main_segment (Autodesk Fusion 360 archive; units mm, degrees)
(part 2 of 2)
sketch "hes slots" plane through (0, -21.9998, 0) normal (0, -1, 0) x axis (1, 0, 0)
  line L1 (261.226, 171.719) -> (259.326, 168.4281)
  line L2 (259.326, 175.0099) -> (261.226, 171.719)
  line L3 (255.526, 175.0099) -> (259.326, 175.0099)
  line L4 (253.626, 171.719) -> (255.526, 175.0099)
  line L5 (255.526, 168.4281) -> (253.626, 171.719)
  line L6 (259.326, 168.4281) -> (255.526, 168.4281)
  line L7 (249.7983, 177.1307) -> (250.2985, 176.2642)
  line L8 (253.67, 180.982) -> (250.311, 179.0427)
  line L9 (259.5563, 179.8293) -> (254.7324, 181.1219)
  line L10 (259.6429, 179.8793) -> (259.5563, 179.8293)
  line L11 (285.6015, 134.9177) -> (259.6429, 179.8793)
  line L12 (285.5149, 134.8677) -> (285.6015, 134.9177)
  line L13 (284.2223, 130.0438) -> (285.5149, 134.8677)
  line L14 (280.211, 127.2543) -> (283.57, 129.1937)
  line L15 (277.7985, 128.6328) -> (278.2985, 127.7668)
  line L16 (274.7469, 128.7184) -> (275.6129, 129.2184)
  line L17 (274.6612, 125.6668) -> (274.1612, 126.5328)
  line L18 (269.9808, 121.3479) -> (274.1488, 123.7543)
  line L19 (270.7612, 118.7963) -> (269.7612, 120.5283)
  line L20 (269.3827, 116.3838) -> (270.2487, 116.8838)
  line L21 (234.9703, 173.1879) -> (267.4703, 116.8963)
  line L22 (236.3487, 175.6003) -> (235.4827, 175.1003)
  line L23 (239.2612, 173.3559) -> (238.2612, 175.0879)
  line L24 (244.2488, 175.5427) -> (240.0808, 173.1362)
  line L25 (246.6612, 174.1642) -> (246.1612, 175.0302)
  line L26 (249.7129, 174.0786) -> (248.8469, 173.5786)
  line L27 (249.8745, 174.1858) -> (249.7129, 174.0786)
  line L28 (250.2988, 176.2638) -> (250.344, 176.1855)
  line L29 (250.8337, 165.719) -> (248.9337, 162.4281)
  line L30 (248.9337, 169.0099) -> (250.8337, 165.719)
  line L31 (245.1337, 169.0099) -> (248.9337, 169.0099)
  line L32 (243.2337, 165.719) -> (245.1337, 169.0099)
  line L33 (245.1337, 162.4281) -> (243.2337, 165.719)
  line L34 (248.9337, 162.4281) -> (245.1337, 162.4281)
  line L35 (263.2337, 131.078) -> (265.1337, 134.3689)
  line L36 (265.1337, 127.7871) -> (263.2337, 131.078)
  line L37 (268.9337, 127.7871) -> (265.1337, 127.7871)
  line L38 (270.8337, 131.078) -> (268.9337, 127.7871)
  line L39 (268.9337, 134.3689) -> (270.8337, 131.078)
  line L40 (265.1337, 134.3689) -> (268.9337, 134.3689)
  line L41 (273.626, 137.078) -> (275.526, 140.3689)
  line L42 (275.526, 133.7871) -> (273.626, 137.078)
  line L43 (279.326, 133.7871) -> (275.526, 133.7871)
  line L44 (281.226, 137.078) -> (279.326, 133.7871)
  line L45 (279.326, 140.3689) -> (281.226, 137.078)
  line L46 (275.526, 140.3689) -> (279.326, 140.3689)
  line L47 (288.3901, 126.0876) -> (253.3901, 186.7094)
  line L48 (189.1191, 226.8415) -> (188.3554, 223.119)
  line L49 (186.2772, 229.3641) -> (189.1191, 226.8415)
  line L50 (182.6716, 228.1642) -> (186.2772, 229.3641)
  line L51 (181.9079, 224.4418) -> (182.6716, 228.1642)
  line L52 (184.7498, 221.9192) -> (181.9079, 224.4418)
  line L53 (188.3554, 223.119) -> (184.7498, 221.9192)
  line L54 (212.1304, 200.7849) -> (215.8279, 201.6616)
  line L55 (211.041, 197.1444) -> (212.1304, 200.7849)
  line L56 (213.6491, 194.3807) -> (211.041, 197.1444)
  line L57 (217.3465, 195.2575) -> (213.6491, 194.3807)
  line L58 (218.4359, 198.8979) -> (217.3465, 195.2575)
  line L59 (215.8279, 201.6616) -> (218.4359, 198.8979)
  line L60 (275.1563, 87.8062) -> (277.7427, 90.5902)
  line L61 (276.2743, 84.1743) -> (275.1563, 87.8062)
  line L62 (279.9785, 83.3266) -> (276.2743, 84.1743)
  line L63 (282.5648, 86.1106) -> (279.9785, 83.3266)
  line L64 (281.4469, 89.7425) -> (282.5648, 86.1106)
  line L65 (277.7427, 90.5902) -> (281.4469, 89.7425)
  line L66 (284.5943, 49.13) -> (287.4996, 51.5793)
  line L67 (285.2629, 45.3893) -> (284.5943, 49.13)
  line L68 (288.8367, 44.0979) -> (285.2629, 45.3893)
  line L69 (291.742, 46.5472) -> (288.8367, 44.0979)
  line L70 (291.0735, 50.288) -> (291.742, 46.5472)
  line L71 (287.4996, 51.5793) -> (291.0735, 50.288)
  circle C1 centre (257.426, 171.719) radius 2.05
  circle C2 centre (247.0337, 165.719) radius 2.05
  circle C3 centre (277.426, 137.078) radius 2.05
  circle C4 centre (267.0337, 131.078) radius 2.05
  arc A1 centre (251.011, 177.8302) radius 1.4 clockwise from (249.7983, 177.1307) to (250.311, 179.0427)
  arc A2 centre (254.37, 179.7696) radius 1.4 clockwise from (253.67, 180.982) to (254.7324, 181.1219)
  arc A3 centre (282.87, 130.4061) radius 1.4 clockwise from (284.2223, 130.0438) to (283.57, 129.1937)
  arc A4 centre (279.511, 128.4668) radius 1.4 clockwise from (280.211, 127.2543) to (278.2985, 127.7668)
  arc A5 centre (276.4129, 127.8328) radius 1.6 clockwise from (275.6129, 129.2184) to (277.7985, 128.6328)
  arc A6 centre (275.5469, 127.3328) radius 1.6 clockwise from (274.1612, 126.5328) to (274.7469, 128.7184)
  arc A7 centre (273.4488, 124.9668) radius 1.4 clockwise from (274.6612, 125.6668) to (274.1488, 123.7543)
  arc A8 centre (270.2808, 120.8283) radius 0.6 clockwise from (269.7612, 120.5283) to (269.9808, 121.3479)
  arc A9 centre (269.5487, 118.0963) radius 1.4 clockwise from (270.7612, 118.7963) to (270.2487, 116.8838)
  arc A10 centre (268.6827, 117.5963) radius 1.4 clockwise from (269.3827, 116.3838) to (267.4703, 116.8963)
  arc A11 centre (236.1827, 173.8879) radius 1.4 clockwise from (234.9703, 173.1879) to (235.4827, 175.1003)
  arc A12 centre (237.0487, 174.3879) radius 1.4 clockwise from (236.3487, 175.6003) to (238.2612, 175.0879)
  arc A13 centre (239.7808, 173.6559) radius 0.6 clockwise from (240.0808, 173.1362) to (239.2612, 173.3559)
  arc A14 centre (244.9488, 174.3302) radius 1.4 clockwise from (244.2488, 175.5427) to (246.1612, 175.0302)
  arc A15 centre (248.0469, 174.9642) radius 1.6 clockwise from (248.8469, 173.5786) to (246.6612, 174.1642)
  arc A16 centre (249.0449, 175.4355) radius 1.5 clockwise from (250.344, 176.1855) to (249.8745, 174.1858)
  arc A17 centre (248.9129, 175.4642) radius 1.6 clockwise from (250.2985, 176.2642) to (250.2988, 176.2638)
  circle C5 centre (185.5135, 225.6416) radius 2
  circle C6 centre (214.7385, 198.0212) radius 2
  circle C7 centre (278.8606, 86.9584) radius 2
  circle C8 centre (288.1682, 47.8386) radius 2
  point P8 (257.426, 171.719)
  point P9 (257.426, 171.719)
  point P10 (247.0337, 165.719)
  point P75 (247.0337, 165.719)
  point P12 (267.0337, 131.078)
  point P82 (267.0337, 131.078)
  point P11 (277.426, 137.078)
  point P89 (277.426, 137.078)
  point P98 (185.5135, 225.6416)
  point P120 (185.5135, 225.6416)
  point P105 (214.7385, 198.0212)
  point P121 (214.7385, 198.0212)
  point P112 (278.8606, 86.9584)
  point P122 (278.8606, 86.9584)
  point P119 (288.1682, 47.8386)
  point P123 (288.1682, 47.8386)
  point P2 (259.326, 168.4281)
  point P69 (248.9337, 162.4281)
  point P76 (265.1337, 134.3689)
  point P83 (275.526, 140.3689)
  point P92 (188.3554, 223.119)
  point P99 (215.8279, 201.6616)
  point P106 (277.7427, 90.5902)
  point P113 (287.4996, 51.5793)
  coincident P8 P9
  coincident P10 P75
  coincident P12 P82
  coincident P11 P89
  parallel L2 L47
  parallel L45 L47
  parallel L39 L47
  parallel L30 L47
  coincident P98 P120
  coincident P105 P121
  coincident P112 P122
  coincident P119 P123
  dimension "d244" distance P2 P8 = 3.8
  dimension "d245" distance P69 P75 = 3.8
  dimension "d246" distance P76 P82 = 3.8
  dimension "d247" distance P83 P89 = 3.8
  dimension "d250" distance P92 P98 = 3.8
  dimension "d251" distance P99 P105 = 3.8
  dimension "d252" distance P106 P112 = 3.8
  dimension "d253" distance P113 P119 = 3.8
extrude "Extrude17" cut sketch "hes slots" profile of L60 L61 L62 L63 L64 L65 L66 L67 L68 L69 L70 L71 blind -6 from offset -10
extrude "Extrude16" cut sketch "hes slots" profile of L1 L2 L3 L4 L5 L6 C1 C2 C3 C4 L29 L30 L31 L32 L33 L34 L35 L36 L37 L38 L39 L40 L41 L42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 against normal blind 2
extrude "Extrude18" cut sketch "hes slots" profile of L48 L49 L50 L51 L52 L53 L54 L55 L56 L57 L58 L59 C5 C6 against normal blind 7
sketch "small pocket" plane through (0, 0.0002, 0) normal (0, 1, 0) x axis (-1, 0, 0)
  line L1 (-144.1577, 247.6885) -> (-142.7926, 247.324)
  line L2 (-170.2702, 243.9555) -> (-163.9732, 235.0401)
  line L3 (-158.9396, 253.2593) -> (-158.1458, 251.9845)
  line L4 (-159.7885, 252.7308) -> (-158.9396, 253.2593)
  line L5 (-171.1402, 245.1776) -> (-159.7885, 252.7308)
  curve K1 (-254.2562, 187.2094) -> (-172.5326, 245.4252)
  line L6 (-256.7562, 182.8793) -> (-254.2562, 187.2094)
  line L7 (-241.3298, 173.9728) -> (-256.7562, 182.8793)
  line L8 (-174.3946, 227.5779) -> (-180.9692, 236.1462)
  line L9 (-294.8797, 38.6359) -> (-284.2856, 37.2412)
  line L10 (-296.7753, 20.7526) -> (-296.6755, 20.7456)
  line L11 (-294.9932, 38.6508) -> (-294.9788, 38.649)
  line L12 (-286.7562, 130.9177) -> (-271.3298, 122.0113)
  line L13 (-289.2562, 126.5876) -> (-286.7562, 130.9177)
  line L14 (-280.6738, 105.4667) -> (-284.1318, 107.4633)
  line L15 (-296.4, 0.9531) -> (-298.9985, 0.9531)
  line L16 (-296.4, 0) -> (-296.4, 0.9531)
  line L17 (-295.3663, -8.8866) -> (-296.2658, -8.9169)
  line L18 (-288.5852, 0) -> (-295.5, 0)
  line L19 (-286.9844, -20.0679) -> (-287.8822, -20.1307)
  line L20 (-286.0549, -19.0005) -> (-286.9844, -20.0679)
  line L21 (-287.0527, -19.0667) -> (-286.0549, -19.0005)
  line L22 (-287.6852, 0.8045) -> (-287.6852, 0)
  line L23 (-285.5841, 0.8045) -> (-287.6852, 0.8045)
  line L24 (-269.3835, 97.7936) -> (-269.4715, 97.8444)
  line L25 (-285.9868, 19.9981) -> (-285.8871, 19.9912)
  line L26 (-252.5241, 186.2094) -> (-240.9703, 179.5388)
  curve K2 (-174.1727, 244.2806) -> (-252.5241, 186.2094)
  line L27 (-182.7946, 238.5269) -> (-174.1727, 244.2806)
  line L28 (-284.1318, 107.4633) -> (-280.6738, 105.4667)
  line L29 (-286.7562, 130.9177) -> (-289.2562, 126.5876)
  line L30 (-286.7562, 130.9177) -> (-271.3298, 122.0113)
  line L31 (-283.1318, 109.1953) -> (-280.67, 107.774)
  line L32 (-286.5241, 127.3197) -> (-287.5241, 125.5876)
  line L33 (-285.1581, 127.6857) -> (-276.2573, 122.5468)
  line L34 (-274.9758, 118.8248) -> (-279.2428, 108.2653)
  arc A1 centre (0, 0) radius 285.5852 clockwise from (-285.5841, 0.8045) to (-142.7926, 247.324)
  arc A2 centre (0, 0) radius 286.5852 clockwise from (-163.9732, 235.0401) to (-144.1577, 247.6885)
  arc A3 centre (0, 0) radius 297.5 clockwise from (-170.2702, 243.9555) to (-158.1458, 251.9845)
  arc A4 centre (-171.7126, 245.9976) radius 1 clockwise from (-171.1402, 245.1776) to (-172.5326, 245.4252)
  arc A5 centre (0.1681, -0.0971) radius 297.6938 clockwise from (-241.3298, 173.9728) to (-180.9692, 236.1462)
  arc A6 centre (0.1681, -0.0971) radius 286.8938 clockwise from (-284.2856, 37.2412) to (-174.3946, 227.5779)
  arc A7 centre (0, 0) radius 297.4 clockwise from (-296.6755, 20.7456) to (-294.8797, 38.6359)
  arc A8 centre (0, 0) radius 297.5 clockwise from (-296.7753, 20.7526) to (-294.9788, 38.649)
  arc A9 centre (0.1681, -0.0971) radius 297.6938 clockwise from (-294.9932, 38.6508) to (-271.3298, 122.0113)
  arc A10 centre (-277.1318, 119.5876) radius 14 clockwise from (-284.1318, 107.4633) to (-289.2562, 126.5876)
  arc A11 centre (-281.1738, 104.6007) radius 1 clockwise from (-280.6738, 105.4667) to (-280.2365, 104.2521)
  arc A12 centre (0, 0) radius 299 clockwise from (-298.9985, 0.9531) to (-280.2365, 104.2521)
  arc A13 centre (0, 0) radius 296.4 clockwise from (-296.2658, -8.9169) to (-296.4, 0)
  arc A14 centre (0, 0) radius 295.5 clockwise from (-295.3663, -8.8866) to (-295.5, 0)
  arc A15 centre (0, 0) radius 288.5852 clockwise from (-287.8822, -20.1307) to (-288.5852, 0)
  arc A16 centre (0, 0) radius 287.6852 clockwise from (-287.0527, -19.0667) to (-287.6852, 0)
  arc A17 centre (0, 0) radius 286.6852 clockwise from (-285.9868, 19.9981) to (-269.4715, 97.8444)
  arc A18 centre (0, 0) radius 286.5852 clockwise from (-285.8871, 19.9912) to (-269.3835, 97.7936)
  arc A19 centre (0.1681, -0.0971) radius 300.6938 clockwise from (-240.9703, 179.5388) to (-182.7946, 238.5269)
  arc A20 centre (-277.1318, 119.5876) radius 14 clockwise from (-284.1318, 107.4633) to (-289.2562, 126.5876)
  arc A21 centre (-277.1318, 119.5876) radius 12 clockwise from (-283.1318, 109.1953) to (-287.5241, 125.5876)
  arc A22 centre (-277.7573, 119.9487) radius 3 clockwise from (-276.2573, 122.5468) to (-274.9758, 118.8248)
  arc A23 centre (-280.17, 108.64) radius 1 clockwise from (-279.2428, 108.2653) to (-280.67, 107.774)
  arc A24 centre (-285.6581, 126.8197) radius 1 clockwise from (-286.5241, 127.3197) to (-285.1581, 127.6857)
  parallel L28 L31
  concentric A20 A21
  parallel L29 L32
  parallel L30 L33
  tangent L31 A21
  tangent A21 L32
  tangent L34 A22
  tangent L33 A22
  tangent L31 A23
  tangent L34 A23
  tangent L32 A24
  tangent L33 A24
  equal A23 A24
  dimension "d260" radius A22 = 3
  dimension "d261" radius A23 = 1
extrude "Extrude19" cut sketch "small pocket" profile of L31 A21 L32 L33 L34 A22 A23 A24 against normal blind 19
fillet "Fillet1" radius 1
extrude "Extrude20" cut sketch "small pocket" profile of L31 A21 L32 L33 L34 A22 A23 A24 along normal blind 18
fillet "Fillet2" radius 1
sketch "screw holes" plane through (0, 22.0002, 0) normal (0, 1, 0) x axis (-1, 0, 0)
  circle C1 centre (-257.426, 171.719) radius 2.05
  circle C2 centre (-277.426, 137.078) radius 2.05
  circle C3 centre (-185.5135, 225.6417) radius 2
  circle C4 centre (-214.7385, 198.0211) radius 2
  circle C5 centre (-247.0337, 165.719) radius 2.05
  circle C6 centre (-267.0337, 131.078) radius 2.05
  circle C7 centre (-278.8606, 86.9584) radius 2
  circle C8 centre (-288.1682, 47.8386) radius 2
  circle C9 centre (-185.5135, 225.6417) radius 3.5
  circle C10 centre (-214.7385, 198.0211) radius 3.5
  circle C11 centre (-247.0337, 165.719) radius 3.5
  circle C12 centre (-257.426, 171.719) radius 3.5
  circle C13 centre (-267.0337, 131.078) radius 3.5
  circle C14 centre (-277.426, 137.078) radius 3.5
  circle C15 centre (-278.8606, 86.9584) radius 3.5
  circle C16 centre (-288.1682, 47.8386) radius 3.5
  concentric C3 C9
  concentric C4 C10
  concentric C5 C11
  concentric C1 C12
  concentric C6 C13
  concentric C2 C14
  concentric C7 C15
  concentric C8 C16
  dimension "d268" diameter C9 = 7
  dimension "d269" diameter C10 = 7
  dimension "d270" diameter C11 = 7
  dimension "d271" diameter C12 = 7
  dimension "d272" diameter C13 = 7
  dimension "d273" diameter C14 = 7
  dimension "d274" diameter C15 = 7
  dimension "d275" diameter C16 = 7
extrude "Extrude21" cut sketch "screw holes" profile of C1 C2 C11 C12 C13 C14 against normal blind 5
extrude "Extrude22" cut sketch "screw holes" profile of C9 C10 against normal blind 9
extrude "Extrude23" cut sketch "screw holes" profile of C15 C16 against normal blind 16
chamfer "Chamfer4" distance 0.5
hole "Hole4" HoleDepth 6.2 HoleDiameter 7.5 TipAngle 180 RefDim1 10 RefDim2 35
hole "Hole2" HoleDepth 6.2 HoleDiameter 7.5 TipAngle 180
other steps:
create_component "CreateComponent1"
remove_body "RemoveBody1"
named bodies: "profile", "top", "bot", "mounting block"

design "mounting plate"
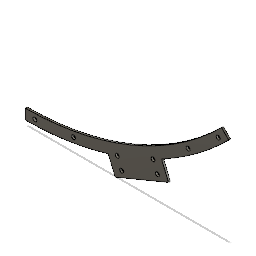
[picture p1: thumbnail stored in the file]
sketch "Sketch1" plane through (0, 0, 0) normal (0, 0, 1) x axis (1, 0, 0)
  line L1 (-0.1099, -297.6938) -> (-0.1099, -286.8938)
  line L2 (210.579, -210.4236) -> (202.9422, -202.7869)
  line L3 (202.9422, -202.7869) -> (-0.1099, -286.8938)
  line L4 (210.579, -210.4236) -> (-0.1099, -297.6938)
  line L5 (139.6676, -337.1874) -> (101.4162, -244.8403)
  line L6 (148.2583, -279.5334) -> (92.8255, -302.4944)
  line L7 (145.9622, -273.9901) -> (90.5294, -296.9511)
  line L8 (141.37, -262.9035) -> (85.9372, -285.8645)
  line L9 (141.0589, -262.1526) -> (148.2583, -279.5334)
  line L10 (92.8255, -302.4944) -> (85.6262, -285.1136)
  arc A1 centre (0, 0) radius 286.8938 clockwise from (202.9422, -202.7869) to (-0.1099, -286.8938)
  arc A2 centre (0, 0) radius 292.2938 clockwise from (206.7621, -206.6038) to (-0.1119, -292.2938)
  circle C1 centre (136.7234, -277.8169) radius 2
  circle C2 centre (99.7682, -293.1243) radius 2
  circle C3 centre (132.1312, -266.7304) radius 2
  circle C4 centre (95.176, -282.0377) radius 2
  circle C5 centre (199.5712, -213.558) radius 2
  circle C6 centre (168.3723, -238.9277) radius 2
  circle C7 centre (9.8901, -292.1264) radius 2
  circle C8 centre (49.8901, -288.0046) radius 2
  arc A3 centre (0, 0) radius 297.6938 clockwise from (85.6262, -285.1136) to (-0.1099, -297.6938)
  arc A4 centre (0, 0) radius 297.6938 clockwise from (210.579, -210.4236) to (141.0589, -262.1526)
  circle C9 centre (0, 0) radius 297.6938
  point P1 (0, 0)
  point P2 (0, 0)
  point P8 (101.4162, -244.8403)
  point P16 (145.9622, -273.9901)
  point P18 (141.37, -262.9035)
  point P19 (136.7234, -277.8169)
  point P20 (99.7682, -293.1243)
  point P21 (132.1312, -266.7304)
  point P22 (95.176, -282.0377)
  point P23 (199.5712, -213.558)
  point P24 (168.3723, -238.9277)
  point P25 (9.8901, -292.1264)
  point P26 (49.8901, -288.0046)
  point P27 (141.0589, -262.1526)
  point P13 (92.8255, -302.4944)
  point P14 (148.2583, -279.5334)
  coincident P1 P2
  concentric A1 A3
  vertical L1
  parallel L3 L4
  midpoint L3 P8
  perpendicular L4 L5
  perpendicular L4 L9
  midpoint L5 L6
  coincident P16 L9
  perpendicular L7 L9
  coincident P18 L9
  perpendicular L8 L9
  coincident L7 P19
  coincident L7 P20
  coincident L8 P21
  coincident L8 P22
  coincident A2 P23
  coincident A2 P24
  coincident A2 P25
  coincident A2 P26
  coincident P27 A3
  concentric A3 A4
  concentric A3 C9
  coincident P27 C9
  dimension "d3" angle L1 L2 = 45
  dimension "d4" = 5.4
  dimension "d5" distance P13 P14 = 60
  dimension "d6" distance L4 L6 = 40
  dimension "d7" distance L6 L7 = 6
  dimension "d8" distance L6 L8 = 18
  dimension "d9" diameter C1 = 4
  dimension "d10" diameter C2 = 4
  dimension "d11" diameter C3 = 4
  dimension "d12" diameter C4 = 4
  dimension "d13" distance P21 L9 = 10
  dimension "d16" distance P19 L9 = 10
  dimension "d17" diameter C5 = 4
  dimension "d18" diameter C6 = 4
  dimension "d19" diameter C7 = 4
  dimension "d20" diameter C8 = 4
  dimension "d21" distance L1 P25 = 10
  dimension "d22" distance L1 P26 = 50
  dimension "d23" distance L2 P23 = 10
  dimension "d24" distance L2 P24 = 50
  dimension "d27" distance A1 A4 = 10.8
extrude "Extrude1" new body sketch "Sketch1" profile of A4 A1 L1 L2 L10 L6 L9 C1 C2 C3 C4 C5 C6 C7 C8 along normal blind 2
sketch "Sketch2" plane through (0, 0, 2) normal (0, 0, 1) x axis (1, 0, 0)
  line L1 (-0.1099, -297.6938) -> (-0.1099, -286.8938)
  line L2 (92.8255, -302.4944) -> (85.6262, -285.1136)
  line L3 (148.2583, -279.5334) -> (92.8255, -302.4944)
  line L4 (141.0589, -262.1526) -> (148.2583, -279.5334)
  line L5 (202.9422, -202.7869) -> (210.579, -210.4236)
  line L6 (141.0589, -262.1526) -> (85.6262, -285.1136)
  circle C1 centre (168.3723, -238.9277) radius 2
  circle C2 centre (9.8901, -292.1264) radius 2
  circle C3 centre (49.8901, -288.0046) radius 2
  circle C4 centre (132.1312, -266.7304) radius 2
  circle C5 centre (95.176, -282.0377) radius 2
  circle C6 centre (199.5712, -213.558) radius 2
  circle C7 centre (99.7682, -293.1243) radius 2
  circle C8 centre (136.7234, -277.8169) radius 2
  arc A1 centre (0, 0) radius 297.6938 clockwise from (85.6262, -285.1136) to (-0.1099, -297.6938)
  arc A2 centre (0, 0) radius 297.6938 clockwise from (210.579, -210.4236) to (141.0589, -262.1526)
  arc A3 centre (0, 0) radius 286.8938 clockwise from (202.9422, -202.7869) to (-0.1099, -286.8938)
  point P12 (85.6262, -285.1136)
  point P19 (85.6262, -285.1136)
  point P16 (141.0589, -262.1526)
  point P20 (141.0589, -262.1526)
  coincident P12 P19
  coincident P16 P20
